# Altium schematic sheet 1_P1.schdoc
size 307 x 218 mm; Symbol: Drawing-Symbol_A4; Device: Drawing-Symbol_A4; @Project Name: MSDRV4; @Page Count: 1; @Update Date: 2025-01-27; @Create Date: 2025-01-27; @Schematic Name: MAX2831_2024_REUSE; @Page No: 1; @Page Name: P1; Company: EasyEDA.com; Version: V1.0; Page Size: A4; @Create Time: 14:20:21; @Update Time: 13:22:36; Width: 1170; Height: 825; Region Start: 1; X Region Count: 6; Y Region Count: 4; Blade Width: 10; Title Block Position: 3; @Board Name: MAX2831_2024_REUSE
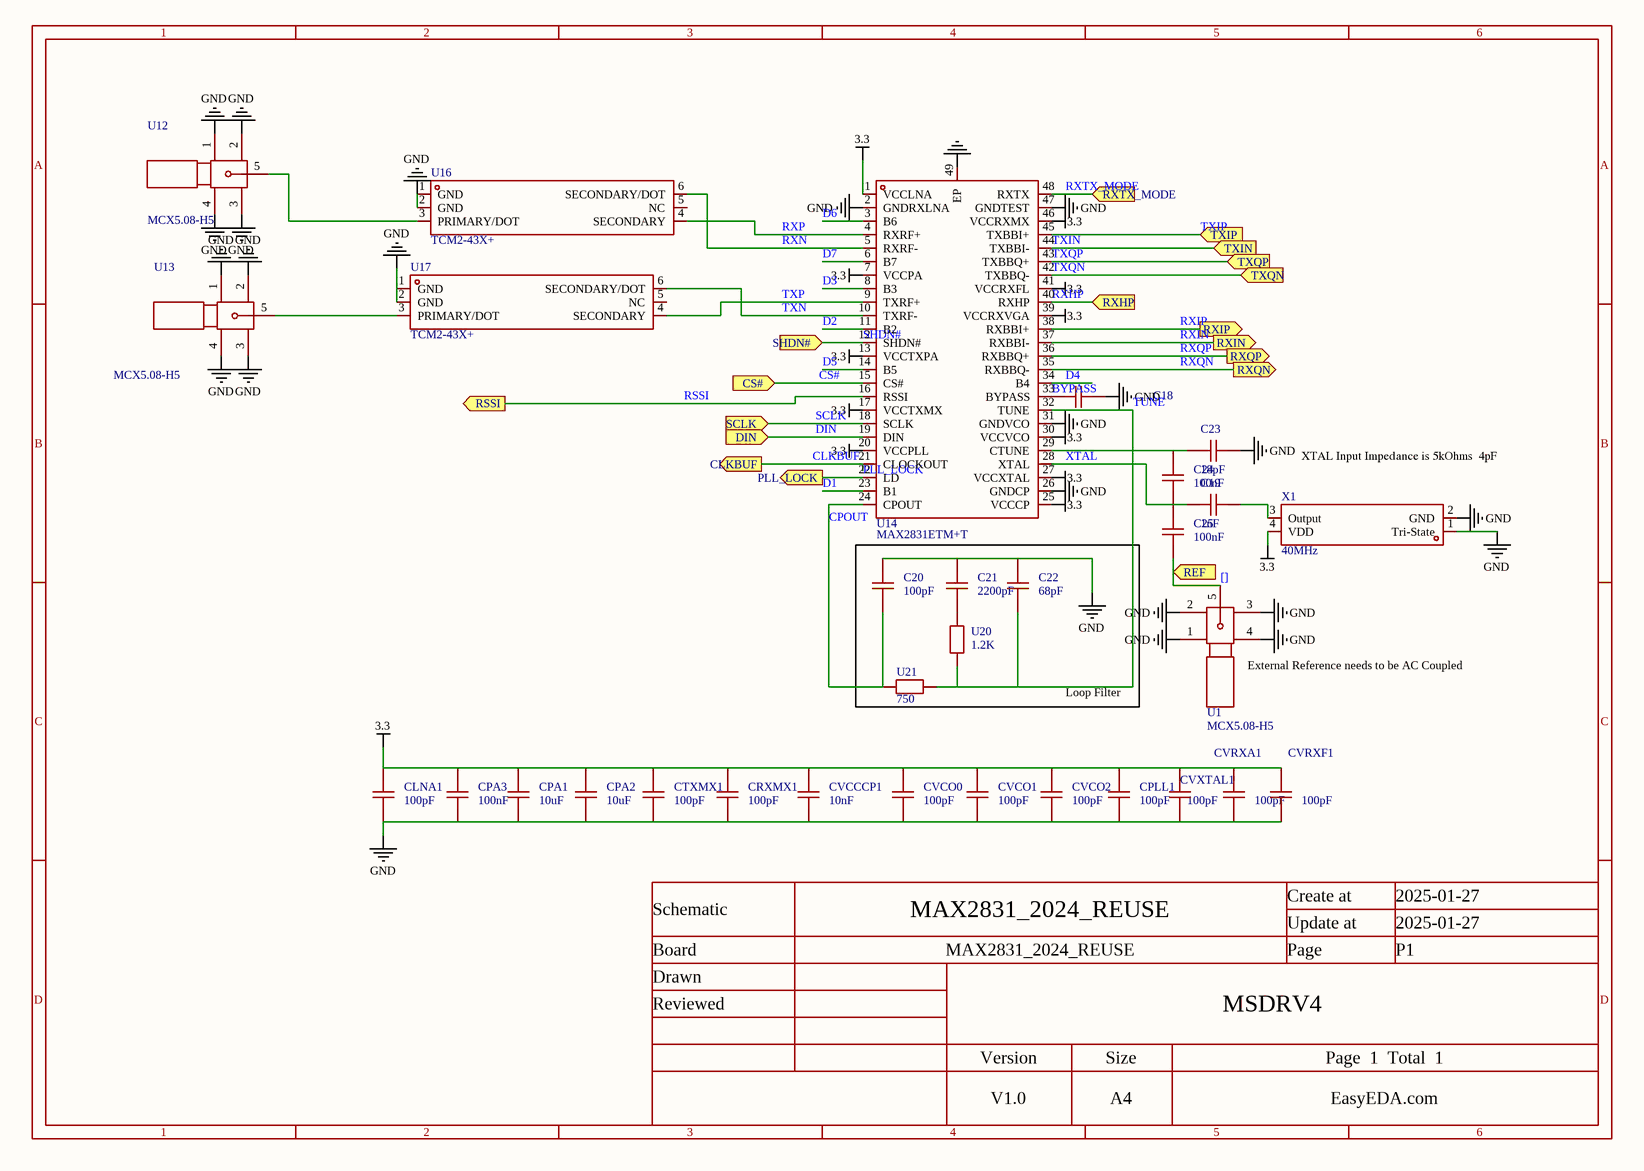
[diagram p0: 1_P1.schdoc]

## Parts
C18  100nF  [C0805]  (value not drawn)
C19  1nF  [C0805]
C20  100pF  [C0805]
C21  2200pF  [C0805]
C22  68pF  [C0805]
C23  18pF  [C0805]
C24  100nF  [C0805]
C25  100nF  [C0805]
CLNA1  100pF  [C0805]
CPA1  10uF  [C0805]
CPA2  10uF  [C0805]
CPA3  100nF  [C0805]
CPLL1  100pF  [C0805]
CRXMX1  100pF  [C0805]
CTXMX1  100pF  [C0805]
CVCCCP1  10nF  [C0805]
CVCO0  100pF  [C0805]
CVCO1  100pF  [C0805]
CVCO2  100pF  [C0805]
CVRXA1  100pF  [C0805]
CVRXF1  100pF  [C0805]
CVXTAL1  100pF  [C0805]
U1  MCX5.08-H5  [SMA-TH_MCX5.08-H5]
U12  MCX5.08-H5  [SMA-TH_MCX5.08-H5]
U13  MCX5.08-H5  [SMA-TH_MCX5.08-H5]
U14  MAX2831ETM+T  [TQFN-48_L7.0-W7.0-P0.50-TL-EP5.6]
U16  TCM2-43X+  [IND-SMD_6P-L4.1-W3.8-P1.27-TL]
U17  TCM2-43X+  [IND-SMD_6P-L4.1-W3.8-P1.27-TL]
U20  1.2K  [R0805]
U21  750  [R0805]
X1  40MHz  [OSC-SMD_4P-L3.2-W2.5-BL]

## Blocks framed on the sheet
Loop Filter: C20-C22 U20 U21

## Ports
CLKBUF (out), CS# (in), DIN (in), PLL_LOCK (out), REF (in), RSSI (out), RXHP (in), RXIN (out), RXIP (out), RXQN (out), RXQP (out), RXTX_MODE (in), SCLK (in), SHDN# (in), TXIN (in), TXIP (in), TXQN (in), TXQP (in)

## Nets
3.3: CLNA1.1 CPA1.1 CPA2.1 CPA3.1 CPLL1.1 CRXMX1.1 CTXMX1.1 CVCCCP1.1 CVCO0.1 CVCO1.1 CVCO2.1 CVRXA1.1 CVRXF1.1 CVXTAL1.1 U14.1(VCCLNA) U14.7(VCCPA) U14.13(VCCTXPA) U14.17(VCCTXMX) U14.20(VCCPLL) U14.25(VCCCP) U14.27(VCCXTAL) U14.30(VCCVCO) U14.39(VCCRXVGA) U14.41(VCCRXFL) U14.46(VCCRXMX) X1.4(VDD)
GND: C18.1 C20.1 C21.1 C22.1 C23.2 CLNA1.2 CPA1.2 CPA2.2 CPA3.2 CPLL1.2 CRXMX1.2 CTXMX1.2 CVCCCP1.2 CVCO0.2 CVCO1.2 CVCO2.2 CVRXA1.2 CVRXF1.2 CVXTAL1.2 U1.1 U1.2 U1.3 U1.4 U12.1 U12.2 U12.3 U12.4 U13.1 U13.2 U13.3 U13.4 U14.2(GNDRXLNA) U14.26(GNDCP) U14.31(GNDVCO) U14.47(GNDTEST) U14.49(EP) U16.1(GND) U16.2(GND) U17.1(GND) U17.2(GND) X1.1(Tri-State) X1.2(GND)
[]: C25.2 U1.5 ; port REF
BYPASS: C18.2 U14.33(BYPASS)
CLKBUF: U14.21(CLOCKOUT) ; port CLKBUF
CPOUT: C20.2 U14.24(CPOUT) U21.2
CS#: U14.15(CS#) ; port CS#
D1: U14.23(B1)
D2: U14.11(B2)
D3: U14.8(B3)
D4: U14.34(B4)
D5: U14.14(B5)
D6: U14.3(B6)
D7: U14.6(B7)
DIN: U14.19(DIN) ; port DIN
PLL_LOCK: U14.22(LD) ; port PLL_LOCK
RSSI: U14.16(RSSI) ; port RSSI
RXHP: U14.40(RXHP) ; port RXHP
RXIN: U14.37(RXBBI-) ; port RXIN
RXIP: U14.38(RXBBI+) ; port RXIP
RXN: U14.5(RXRF-) U16.6(SECONDARY/DOT)
RXP: U14.4(RXRF+) U16.4(SECONDARY)
RXQN: U14.35(RXBBQ-) ; port RXQN
RXQP: U14.36(RXBBQ+) ; port RXQP
RXTX_MODE: U14.48(RXTX) ; port RXTX_MODE
SCLK: U14.18(SCLK) ; port SCLK
SHDN#: U14.12(SHDN#) ; port SHDN#
TUNE: C22.2 U14.32(TUNE) U20.1 U21.1
TXIN: U14.44(TXBBI-) ; port TXIN
TXIP: U14.45(TXBBI+) ; port TXIP
TXN: U14.10(TXRF-) U17.6(SECONDARY/DOT)
TXP: U14.9(TXRF+) U17.4(SECONDARY)
TXQN: U14.42(TXBBQ-) ; port TXQN
TXQP: U14.43(TXBBQ+) ; port TXQP
XTAL: C19.2 C24.2 C25.1 U14.28(XTAL)
NetC19_1: C19.1 X1.3(Output)
NetC21_2: C21.2 U20.2
NetC23_1: C23.1 C24.1 U14.29(CTUNE)
NetU12_5: U12.5 U16.3(PRIMARY/DOT)
NetU13_5: U13.5 U17.3(PRIMARY/DOT)

Not connected (* = marked no-connect by the designer): U16 5(NC); U17 5(NC)

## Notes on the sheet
- XTAL Input Impedance is 5kOhms4pF
- (near U1) External Reference needs to be AC Coupled

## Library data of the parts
C18-C23 CLNA1 CPA1-CPA3 CPLL1 CRXMX1 CTXMX1 CVCCCP1 CVCO0-CVCO2 CVRXA1 CVRXF1 CVXTAL1 = CAP_0603: Symbol: CAP; Convert to PCB: yes
C24 C25 = CAP_0805: Symbol: CAP; Convert to PCB: yes
U1 U12 U13 = MCX5.08-H5_C9900009324: Add into BOM: yes
U14 = MAX2831ETM+T: Manufacturer: ADI(亚德诺)/MAXIM(美信); Add into BOM: yes; Frequency Range: 2.4GHz; Interface: SPI; Operating Voltage: 2.7V~3.6V; Output Power: 21dBm; Data Rate: 54Mbps; Current Of Transmitting: 82mA; Sensitivity: -76dBm; Receive Current: 62mA
U16 U17 = TCM2-43X+: Manufacturer: Mini-Circuits; Add into BOM: yes; Frequency Range: 10MHz~4GHz; Impedance Ratio-Unbalanced/Balanced: 1:2; Insertion Loss (Max): 3dB; Phase Balance: 7°; Return Loss (Min): 14.98dB
U20 U21 = SCR0805J1M: Manufacturer: VO(翔胜); Add into BOM: yes; Tolerance: ±5%
X1 = SX3M40.000E20F30THN: Manufacturer: SCTF(星通时频); Add into BOM: yes; Normal temperature Frequency Tolerance: ±20ppm; Output Type: CMOS; Supply Voltage: 1.2V; Supply Current (Max): 2mA; Frequency Stability: ±30ppm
